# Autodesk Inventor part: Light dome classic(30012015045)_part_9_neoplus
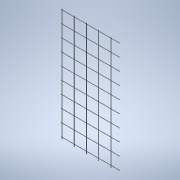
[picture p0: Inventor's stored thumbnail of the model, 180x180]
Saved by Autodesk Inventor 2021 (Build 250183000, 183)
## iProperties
Created: 2026-04
Part Number: Light dome classic(30012015045)_part_9_neoplus
Material: Generic
Catalog Web Link: www.3dfindit.com
Description: Light dome classic_part_9_neoplus-
Vendor: KINGSPAN
Document SubType Name: Modeling
Designer: psAdmin
Manufacturer: KINGSPAN
Mass: 184.33 g
Surface Area: 1482.66 cm^2
Volume: 184.33 cm^3
Density: 1 g/cm^3
Appearance: PSOLRGB-255-255-255
Category: PARTsolutions
Company: KINGSPAN
Title: Light dome classic(30012015045)_part_9_neoplus
Author: Cadenas PARTsolutions
PSOL_IDENT_0: {$CADENAS_DATA/23d-libs/kingspan_kla/light_dome_classic_neoplus/parts/part_9.prj},278 {VTYP=3D},{NB=
PSOL_IDENT_1: Light dome classic(30012015045)_part_9_neoplus},{LINA=Light dome classic(30012015045)_part_9_neoplus
PSOL_IDENT_2: },{NN=Light dome classic_part_9_neoplus},{DATE=15.07.2024 10:56:16},{GEOMDATE=28.06.2024 12:22:18},{
PSOL_IDENT_3: VERSION=},{LINEID=10},{WBVAR=LODLEVEL,L,W,DP,OP},{WBNUMERIC=W}  {NB=Light dome classic(30012015045)_
PSOL_IDENT_4: part_9_neoplus},{LINA=Light dome classic(30012015045)_part_9_neoplus},{KT=DUMMY},{IDNR=},{PN=Light d
PSOL_IDENT_5: ome classic},{LODLEVEL=300},{L=120},{W=150},{WX=120,150,180,240,270,300},{LX=1200},{XWX=1500},{DP=4}
PSOL_IDENT_6: ,{OPX='5','Pneumatic - NRWG F.6 LK'},{OP=5},{DRIVE=1},{DPX='1', 'Natural ventilation', '2' , 'NSHEV
PSOL_IDENT_7: (natural smoke, heat exhaust ventilation)', '3', 'Fixed','4','NSHE'}
NB: Light dome classic(30012015045)_part_9_neoplus
NN: Light dome classic_part_9_neoplus
NBSYN: $PN.($LODLEVEL.$L.$W.$DP.$OP.)_part_9_neoplus
LINA: Light dome classic(30012015045)_part_9_neoplus
CATALOG: Light + Air
PN: Light dome classic
LODLEVEL: 300
L: 120
W: 150
DP: NSHE
OP: Pneumatic - NRWG F.6 LK
SUPPLIER: KINGSPAN
ARTICLENO: Light dome classic(30012015045)_part_9_neoplus
BOMINFO: Light dome classic(30012015045)_part_9_neoplus
CREATOR: CADENAS GmbH
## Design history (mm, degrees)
sketch "Sketch_8"
  geometry: C1 r 2.5 at (450, 263.34); 1 further point
  constraints: 1 centre point
extrude "Extrusion1" join sketch "Sketch_8" stored distance "d0" = 1225; taper "d1" = 0 deg
sketch "Sketch_1"
  geometry: C1 r 2.5 at (-600, 268.32); 1 further point
  constraints: 1 centre point
extrude "Extrusion2" join sketch "Sketch_1" stored distance "d2" = 925; taper "d3" = 0 deg
pattern_linear "Rectangular Pattern1" dims "d6" = 100, "d9" = 0
sketch "Sketch_2"
  geometry: C1 r 2.5 at (350, 263.34); 1 further point
  constraints: 1 centre point
extrude "Extrusion3" join sketch "Sketch_2" stored distance "d10" = 1225; taper "d11" = 0 deg
pattern_linear "Rectangular Pattern2" dims "d14" = 100, "d17" = 0
sketch "Sketch_9"
  geometry: L1 (-10, -278.32)-(10, -278.32); L2 (10, -278.32)-(10, -258.32); L3 (10, -258.32)-(-10, -258.32); L4 (-10, -258.32)-(-10, -278.32)
  constraints: 8 end point
extrude "Extrusion4" cut sketch "Sketch_9" stored distance "d18" = 220; taper "d19" = 0 deg
sketch "Sketch_10"
  geometry: L1 (-500, 497.5)-(-500, -497.5); L2 (-500, -497.5)-(0, -497.5); L3 (0, -497.5)-(0, 497.5); L4 (0, 497.5)-(-500, 497.5)
  constraints: 8 end point
extrude "Extrusion5" cut sketch "Sketch_10" distance "d20" = 1635; taper "d21" = 0 deg
node "IP_9_XY"
node "IP_9_YZ"
node "IP_9_ZX"
node "IP_9_X"
node "IP_9_Y"
node "IP_9_Z"
node "IP_9_Center"
body "Solid1"
